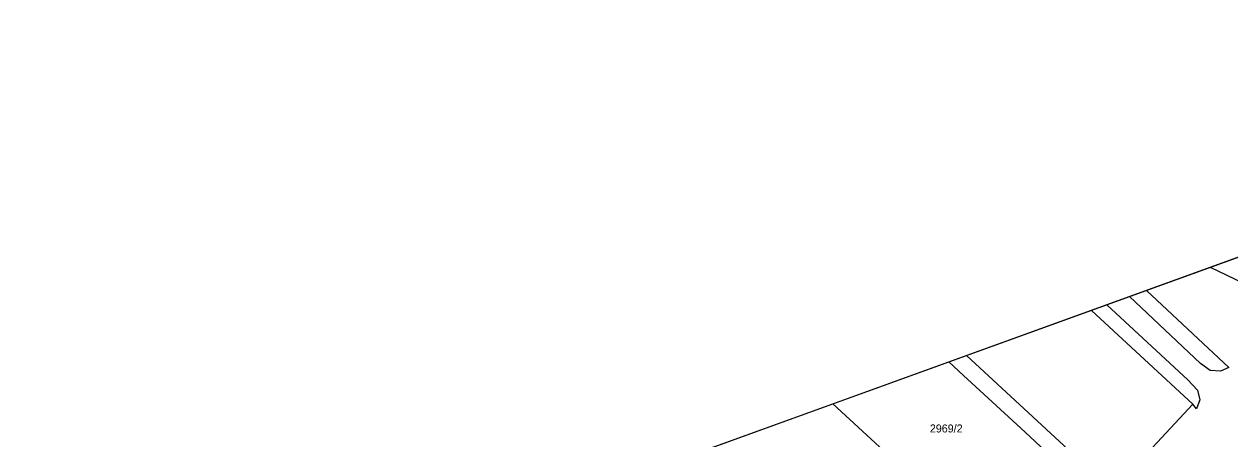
# Model space of a CAD drawing. Extents: x -620552 to -620056, y -1123312 to -1122890.
# Drawn here: x -620552.1 to -620295.9, y -1122977.8 to -1122889.6 of the extents above; entities that cross this region are included whole.
import ezdxf

# ---------------------------------------------------------------- set-up
doc = ezdxf.new("R2010")
doc.units = 0
for name, color, linetype in [('Hranice parcel', 7, 'Continuous'), ('Parcelní čísla', 7, 'Continuous'), ('Rámečky', 7, 'Continuous'), ('Rámečky-tisk', 7, 'Continuous'), ('VAS vodovod', 7, 'Continuous'), ('Vnitřní kresba', 7, 'Continuous')]:
    doc.layers.add(name, color=color, linetype=linetype)

msp = doc.modelspace()

# ---------------------------------------------------------------- linework, layer by layer
at = {"layer": 'Hranice parcel'}
for points in [[(-620325.34, -1122950.49), (-620303.81, -1122970.47), (-620320.91, -1122988.8), (-620351.92, -1122960.11)], [(-620380.28, -1122970.38), (-620346.89, -1123001.2)]]:
    msp.add_lwpolyline(points, dxfattribs=at)
at = {"layer": 'Rámečky'}
msp.add_line((-620157.19, -1122889.6), (-620552.1, -1123032.6), dxfattribs=at)
at = {"layer": 'Rámečky-tisk'}
msp.add_lwpolyline([(-620450.98, -1123311.85), (-620056.07, -1123168.86), (-620157.19, -1122889.6), (-620552.1, -1123032.6)], dxfattribs=at)
at = {"layer": 'VAS vodovod'}
msp.add_lwpolyline([(-620260.52, -1122971.14), (-620273.97, -1122979.53), (-620287.42, -1122987.93), (-620297.29, -1122993.57), (-620307.15, -1122999.21), (-620314.18, -1123003.29), (-620314.33, -1123003.39), (-620314.47, -1123003.48), (-620314.66, -1123003.17), (-620315.7, -1123001.56), (-620316.76, -1122999.96), (-620318.4, -1122997.49), (-620320.04, -1122995.03), (-620321.07, -1122993.52), (-620323.65, -1122991.1), (-620326.23, -1122988.68), (-620330.65, -1122984.59), (-620335.07, -1122980.5), (-620339.44, -1122976.42), (-620343.82, -1122972.33), (-620352.52, -1122964.33), (-620355.63, -1122961.46)], dxfattribs=at)
at = {"layer": 'Vnitřní kresba'}
for p, q in [((-620300.09, -1122941.34), (-620300.01, -1122941.39)), ((-620300.01, -1122941.39), (-620293.37, -1122944.55)), ((-620302.2, -1122961.76), (-620317.24, -1122947.56)), ((-620313.63, -1122946.25), (-620296.17, -1122962.67)), ((-620322.07, -1122949.31), (-620304.85, -1122965.25)), ((-620300.14, -1122963.26), (-620302.2, -1122961.76)), ((-620297.96, -1122963.41), (-620300.14, -1122963.26)), ((-620296.17, -1122962.67), (-620297.96, -1122963.41)), ((-620304.85, -1122965.25), (-620302.84, -1122967.46)), ((-620302.84, -1122967.46), (-620302.33, -1122969.49)), ((-620303.05, -1122971.44), (-620303.81, -1122970.47)), ((-620302.33, -1122969.49), (-620303.05, -1122971.44))]:
    msp.add_line(p, q, dxfattribs=at)

# ---------------------------------------------------------------- texts
at = {"layer": 'Parcelní čísla'}
msp.add_text('2969/2', height=1.7, dxfattribs=at).set_placement((-620359.68, -1122976.46))

doc.saveas('drawing.dxf')
